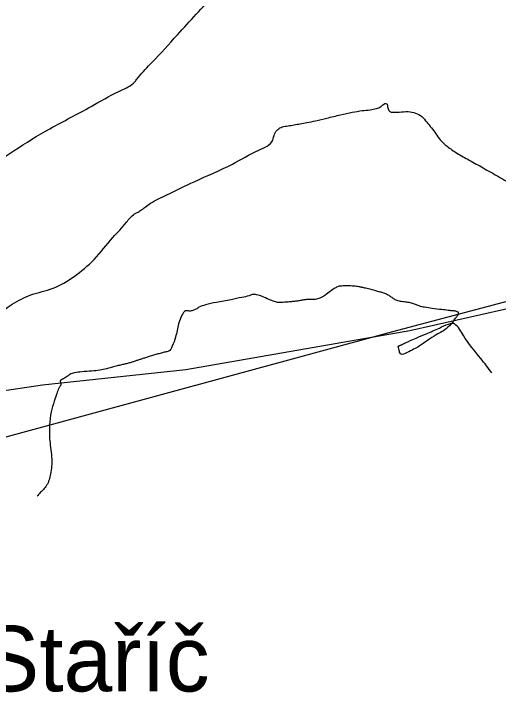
# Model space of a CAD drawing. Extents: x -478495 to -472450, y -1118050 to -1113745.
# Drawn here: x -473518.6 to -473370.5, y -1115865.7 to -1115658.3 of the extents above; entities that cross this region are included whole.
import ezdxf

# ---------------------------------------------------------------- set-up
doc = ezdxf.new("R2010")
doc.units = 0
for name, color, linetype in [('cyklostezka', 7, 'Continuous'), ('hranice kú', 7, 'Continuous'), ('ObPÚ', 7, 'Continuous'), ('okolní k_ú_', 7, 'Continuous'), ('Vrstevnice_vedlejsi', 7, 'Continuous')]:
    doc.layers.add(name, color=color, linetype=linetype)

msp = doc.modelspace()

# ---------------------------------------------------------------- linework, layer by layer
at = {"layer": 'cyklostezka'}
msp.add_lwpolyline([(-473759, -1115660.97), (-473665.89, -1115725.18), (-473621.14, -1115747.34), (-473593.57, -1115765.43), (-473581.37, -1115769.73), (-473564.87, -1115771.76), (-473540.91, -1115773.57), (-473526.9, -1115774.25), (-473509.73, -1115771.76), (-473466, -1115767.07), (-473397.63, -1115755.2), (-473325.31, -1115738.81), (-473271.07, -1115722.98), (-473223.05, -1115702.06), (-473192.54, -1115682.85), (-473154.12, -1115678.32)], dxfattribs=at)
at = {"layer": 'hranice kú'}
for p, q in [((-473402.81, -1115755.42), (-473308.34, -1115730.54)), ((-473570.62, -1115801.12), (-473402.81, -1115755.42))]:
    msp.add_line(p, q, dxfattribs=at)
at = {"layer": 'ObPÚ'}
for p, q in [((-473402.81, -1115755.42), (-473308.34, -1115730.54)), ((-473570.62, -1115801.12), (-473402.81, -1115755.42))]:
    msp.add_line(p, q, dxfattribs=at)
at = {"layer": 'Vrstevnice_vedlejsi'}
for points in [[(-473321.51, -1115691.53), (-473322.12, -1115690.99), (-473323.04, -1115690.14), (-473324.26, -1115688.99), (-473325.78, -1115687.52), (-473327.03, -1115686.28), (-473328.01, -1115685.25), (-473328.72, -1115684.45), (-473329.7, -1115683.42), (-473330.94, -1115682.16), (-473332.44, -1115680.67), (-473333.66, -1115679.45), (-473334.6, -1115678.5), (-473335.25, -1115677.8), (-473335.86, -1115677.2), (-473336.43, -1115676.68), (-473336.95, -1115676.26), (-473337.91, -1115675.38), (-473339.31, -1115674.04), (-473341.16, -1115672.25), (-473342.55, -1115670.87), (-473343.48, -1115669.9), (-473343.95, -1115669.34), (-473344.36, -1115668.86), (-473344.72, -1115668.47), (-473345.03, -1115668.16), (-473345.37, -1115667.78), (-473345.73, -1115667.35), (-473346.13, -1115666.87), (-473346.85, -1115666.07), (-473347.88, -1115664.96), (-473349.22, -1115663.55), (-473350.27, -1115662.45), (-473351.01, -1115661.66), (-473351.44, -1115661.18), (-473352.08, -1115660.5), (-473352.92, -1115659.62), (-473353.97, -1115658.55), (-473355.16, -1115657.35), (-473356.48, -1115656.03), (-473357.93, -1115654.57), (-473359.1, -1115653.37), (-473359.97, -1115652.41), (-473360.55, -1115651.69), (-473361.4, -1115650.64), (-473362.52, -1115649.25), (-473363.91, -1115647.53), (-473365.06, -1115646.17), (-473365.98, -1115645.16), (-473366.67, -1115644.52), (-473367.43, -1115643.78), (-473368.26, -1115642.96), (-473369.16, -1115642.03), (-473370.33, -1115640.83), (-473371.78, -1115639.34), (-473373.49, -1115637.57), (-473374.89, -1115636.1), (-473375.97, -1115634.95), (-473376.73, -1115634.1), (-473377.3, -1115633.41), (-473377.69, -1115632.89), (-473377.9, -1115632.53), (-473378.26, -1115632.05), (-473378.76, -1115631.46), (-473379.41, -1115630.76), (-473380, -1115630.21), (-473380.53, -1115629.82), (-473381.01, -1115629.6), (-473381.56, -1115629.24), (-473382.18, -1115628.74), (-473382.87, -1115628.11), (-473383.71, -1115627.29), (-473384.69, -1115626.28), (-473385.82, -1115625.08), (-473386.92, -1115623.93), (-473387.98, -1115622.82), (-473389.01, -1115621.76), (-473390.01, -1115620.74), (-473390.98, -1115619.77), (-473391.94, -1115618.85), (-473392.84, -1115617.97), (-473393.68, -1115617.13), (-473394.47, -1115616.34), (-473395.26, -1115615.51), (-473396.04, -1115614.65), (-473396.83, -1115613.75), (-473397.58, -1115612.92), (-473398.29, -1115612.17), (-473398.96, -1115611.49), (-473399.69, -1115610.71), (-473400.49, -1115609.84), (-473401.34, -1115608.86), (-473402.17, -1115607.96), (-473402.96, -1115607.12), (-473403.73, -1115606.35), (-473404.5, -1115605.57), (-473405.28, -1115604.78)], [(-473611.8, -1115785.4), (-473607.05, -1115778.02), (-473603.81, -1115773.04), (-473602.1, -1115770.45), (-473601.89, -1115770.24), (-473601.78, -1115770.05), (-473601.76, -1115769.88), (-473601.82, -1115769.72), (-473601.87, -1115769.61), (-473601.9, -1115769.54), (-473601.92, -1115769.52), (-473601.94, -1115769.5), (-473601.96, -1115769.47), (-473601.98, -1115769.43), (-473602.39, -1115768.8), (-473603.18, -1115767.59), (-473604.36, -1115765.78), (-473605.16, -1115764.47), (-473605.59, -1115763.64), (-473605.66, -1115763.3), (-473605.79, -1115762.87), (-473606.01, -1115762.34), (-473606.29, -1115761.72), (-473606.42, -1115761.12), (-473606.39, -1115760.54), (-473606.2, -1115759.98), (-473606.1, -1115759.41), (-473606.1, -1115758.84), (-473606.21, -1115758.27), (-473606.09, -1115757.95), (-473605.76, -1115757.89), (-473605.22, -1115758.1), (-473604.78, -1115758.23), (-473604.46, -1115758.29), (-473604.24, -1115758.27), (-473603.91, -1115758.35), (-473603.47, -1115758.53), (-473602.92, -1115758.79), (-473602.29, -1115759.1), (-473601.58, -1115759.43), (-473600.79, -1115759.8), (-473600.19, -1115760.09), (-473599.76, -1115760.3), (-473599.51, -1115760.43), (-473599.3, -1115760.52), (-473599.16, -1115760.59), (-473599.07, -1115760.61), (-473598.93, -1115760.65), (-473598.75, -1115760.71), (-473598.53, -1115760.79), (-473598.04, -1115760.57), (-473597.28, -1115760.06), (-473596.25, -1115759.26), (-473595.21, -1115758.39), (-473594.16, -1115757.47), (-473593.11, -1115756.48), (-473592.12, -1115755.66), (-473591.21, -1115755), (-473590.37, -1115754.51), (-473588.01, -1115753.03), (-473584.15, -1115750.54), (-473578.77, -1115747.05), (-473573.7, -1115744.5), (-473568.93, -1115742.9), (-473564.46, -1115742.24), (-473559.64, -1115739.4), (-473554.44, -1115734.38), (-473548.89, -1115727.19), (-473542.59, -1115720.2), (-473535.55, -1115713.42), (-473527.78, -1115706.84), (-473518.41, -1115700.2), (-473507.46, -1115693.51), (-473494.92, -1115686.75), (-473486.42, -1115682.12), (-473481.98, -1115679.6), (-473481.58, -1115679.21), (-473481.19, -1115678.77), (-473480.79, -1115678.28), (-473480.4, -1115677.76), (-473476.31, -1115673.27), (-473468.54, -1115664.82), (-473457.09, -1115652.41), (-473448.83, -1115643.71), (-473443.76, -1115638.72), (-473441.88, -1115637.43), (-473440.01, -1115635.86), (-473438.16, -1115634.01), (-473436.32, -1115631.88), (-473434.68, -1115630.26), (-473433.23, -1115629.16), (-473431.99, -1115628.58), (-473429.69, -1115627.07), (-473426.33, -1115624.61), (-473421.92, -1115621.21), (-473418.94, -1115618.9), (-473417.38, -1115617.7)], [(-473567.7, -1115770.86), (-473567.61, -1115770.53), (-473567.36, -1115770.27), (-473566.97, -1115770.1), (-473566.42, -1115770.01), (-473565.94, -1115769.92), (-473565.54, -1115769.83), (-473565.22, -1115769.75), (-473564.7, -1115769.66), (-473564, -1115769.55), (-473563.1, -1115769.43), (-473562.46, -1115769.35), (-473562.06, -1115769.31), (-473561.91, -1115769.32), (-473561.63, -1115769.32), (-473561.23, -1115769.31), (-473560.7, -1115769.29), (-473560.09, -1115769.27), (-473559.4, -1115769.25), (-473558.62, -1115769.23), (-473557.61, -1115769.17), (-473556.36, -1115769.08), (-473554.87, -1115768.96), (-473553.85, -1115768.88), (-473553.31, -1115768.84), (-473553.25, -1115768.83), (-473553.07, -1115768.84), (-473552.77, -1115768.85), (-473552.36, -1115768.88), (-473551.64, -1115768.9), (-473550.6, -1115768.93), (-473549.26, -1115768.95), (-473547.97, -1115768.88), (-473546.75, -1115768.7), (-473545.58, -1115768.41), (-473543.31, -1115767.31), (-473539.93, -1115765.42), (-473535.45, -1115762.71), (-473531.25, -1115759.38), (-473527.31, -1115755.43), (-473523.66, -1115750.86), (-473518.97, -1115747.14), (-473513.26, -1115744.26), (-473506.52, -1115742.24), (-473500.1, -1115738.65), (-473494, -1115733.48), (-473488.23, -1115726.74), (-473484.1, -1115722.1), (-473481.63, -1115719.56), (-473480.82, -1115719.12), (-473479.73, -1115718.43), (-473478.37, -1115717.49), (-473476.73, -1115716.29), (-473471.75, -1115713.7), (-473463.4, -1115709.7), (-473451.7, -1115704.3), (-473443.71, -1115700.07), (-473439.44, -1115697.02), (-473438.88, -1115695.14), (-473437.91, -1115693.78), (-473436.54, -1115692.95), (-473434.76, -1115692.64), (-473432.92, -1115692.33), (-473431.03, -1115692), (-473429.07, -1115691.67), (-473426.37, -1115691.1), (-473422.93, -1115690.3), (-473418.75, -1115689.27), (-473415.15, -1115688.51), (-473412.14, -1115688), (-473409.71, -1115687.75), (-473407.8, -1115687.33), (-473406.42, -1115686.76), (-473405.55, -1115686.02), (-473404.92, -1115685.78), (-473404.53, -1115686.05), (-473404.37, -1115686.81), (-473404.18, -1115687.44), (-473403.97, -1115687.92), (-473403.74, -1115688.25), (-473402.68, -1115688.42), (-473400.81, -1115688.44), (-473398.11, -1115688.3), (-473395.81, -1115688.76), (-473393.92, -1115689.83), (-473392.42, -1115691.5), (-473390.99, -1115693.23), (-473389.62, -1115695.04), (-473388.32, -1115696.92), (-473386.19, -1115698.89), (-473383.23, -1115700.96), (-473379.42, -1115703.11), (-473375.2, -1115705.5), (-473370.56, -1115708.11), (-473365.5, -1115710.96), (-473361.58, -1115712.26), (-473358.81, -1115712.03)], [(-473372.55, -1115768.13), (-473375.9, -1115763.71), (-473381.25, -1115756.69), (-473383.99, -1115753.13), (-473384.14, -1115753.04), (-473385.98, -1115754.15), (-473389.52, -1115756.45), (-473394.76, -1115759.94), (-473398.39, -1115761.89), (-473400.42, -1115762.28), (-473400.84, -1115761.13), (-473401.06, -1115760.35), (-473401.1, -1115759.93), (-473400.95, -1115759.88), (-473400.74, -1115759.78), (-473400.45, -1115759.65), (-473400.1, -1115759.48), (-473399.52, -1115759.2), (-473398.71, -1115758.83), (-473397.68, -1115758.35), (-473395.63, -1115757.46), (-473392.58, -1115756.14), (-473388.52, -1115754.4), (-473385.78, -1115753.19), (-473384.38, -1115752.5), (-473384.3, -1115752.33), (-473384.05, -1115751.96), (-473383.62, -1115751.39), (-473383.02, -1115750.61), (-473382.72, -1115750.04), (-473382.71, -1115749.67), (-473383, -1115749.49), (-473383.33, -1115749.35), (-473383.69, -1115749.24), (-473384.09, -1115749.16), (-473384.4, -1115749.11), (-473384.63, -1115749.09), (-473384.78, -1115749.1), (-473385.85, -1115749), (-473387.84, -1115748.78), (-473390.76, -1115748.45), (-473393.07, -1115748.07), (-473394.76, -1115747.65), (-473395.84, -1115747.19), (-473397.1, -1115746.81), (-473398.52, -1115746.52), (-473400.1, -1115746.31), (-473401.46, -1115745.96), (-473402.58, -1115745.45), (-473403.46, -1115744.78), (-473404.43, -1115744.22), (-473405.5, -1115743.76), (-473406.66, -1115743.41), (-473407.96, -1115743.04), (-473409.4, -1115742.66), (-473410.99, -1115742.27), (-473412.25, -1115741.97), (-473413.2, -1115741.77), (-473413.83, -1115741.67), (-473414.67, -1115741.6), (-473415.7, -1115741.55), (-473416.93, -1115741.52), (-473417.97, -1115741.54), (-473418.81, -1115741.61), (-473419.45, -1115741.72), (-473420.45, -1115742.22), (-473421.8, -1115743.12), (-473423.51, -1115744.41), (-473425.06, -1115745.26), (-473426.46, -1115745.67), (-473427.69, -1115745.65), (-473428.87, -1115745.7), (-473429.98, -1115745.82), (-473431.04, -1115746.02), (-473432.18, -1115746.2), (-473433.39, -1115746.34), (-473434.68, -1115746.45), (-473435.83, -1115746.53), (-473436.83, -1115746.58), (-473437.67, -1115746.6), (-473438.92, -1115746.3), (-473440.58, -1115745.67), (-473442.64, -1115744.72), (-473444.35, -1115744.21), (-473445.69, -1115744.15), (-473446.68, -1115744.53), (-473448.84, -1115745.06), (-473452.16, -1115745.74), (-473456.65, -1115746.56), (-473459.93, -1115747.33), (-473462.01, -1115748.02)], [(-473462.01, -1115748.02), (-473462.89, -1115748.66), (-473463.86, -1115749.05), (-473464.92, -1115749.21), (-473466.07, -1115749.13), (-473467.15, -1115750.44), (-473468.17, -1115753.12), (-473469.12, -1115757.18), (-473470.12, -1115759.98), (-473471.19, -1115761.5), (-473472.3, -1115761.75), (-473473.51, -1115762.05), (-473474.8, -1115762.41), (-473476.19, -1115762.82), (-473477.44, -1115763.21), (-473478.56, -1115763.56), (-473479.56, -1115763.88), (-473480.54, -1115764.2), (-473481.49, -1115764.52), (-473482.43, -1115764.83), (-473483.48, -1115765.13), (-473484.65, -1115765.43), (-473485.93, -1115765.71), (-473487.29, -1115766.05), (-473488.72, -1115766.44), (-473490.22, -1115766.89), (-473492.23, -1115767.26), (-473494.73, -1115767.55), (-473497.73, -1115767.77), (-473499.96, -1115768.1), (-473501.39, -1115768.54), (-473502.05, -1115769.09), (-473502.7, -1115769.55), (-473503.34, -1115769.91), (-473503.97, -1115770.18), (-473504.32, -1115770.46), (-473504.36, -1115770.75), (-473504.12, -1115771.05), (-473504.1, -1115771.49), (-473504.3, -1115772.08), (-473504.73, -1115772.81), (-473505.33, -1115774.38), (-473506.12, -1115776.77), (-473507.1, -1115780), (-473507.56, -1115784.01), (-473507.5, -1115788.82), (-473506.93, -1115794.41), (-473507.25, -1115798.95), (-473508.47, -1115802.44), (-473510.58, -1115804.87), (-473511.36, -1115805.71)]]:
    msp.add_spline(points, degree=3, dxfattribs=at)

# ---------------------------------------------------------------- texts
at = {"layer": 'okolní k_ú_'}
msp.add_text('k.ú. Staříč', height=20, rotation=359.9619, dxfattribs=at).set_placement((-473579.12, -1115865.33))

doc.saveas('drawing.dxf')
